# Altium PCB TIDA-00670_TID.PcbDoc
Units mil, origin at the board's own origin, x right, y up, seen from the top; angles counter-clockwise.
Board outline 1400 x 2800 mil, 2 copper layers (Top Layer, Bottom Layer), stack 62 mil thick; 53 components, 34 nets, 124 pads, 19 vias.
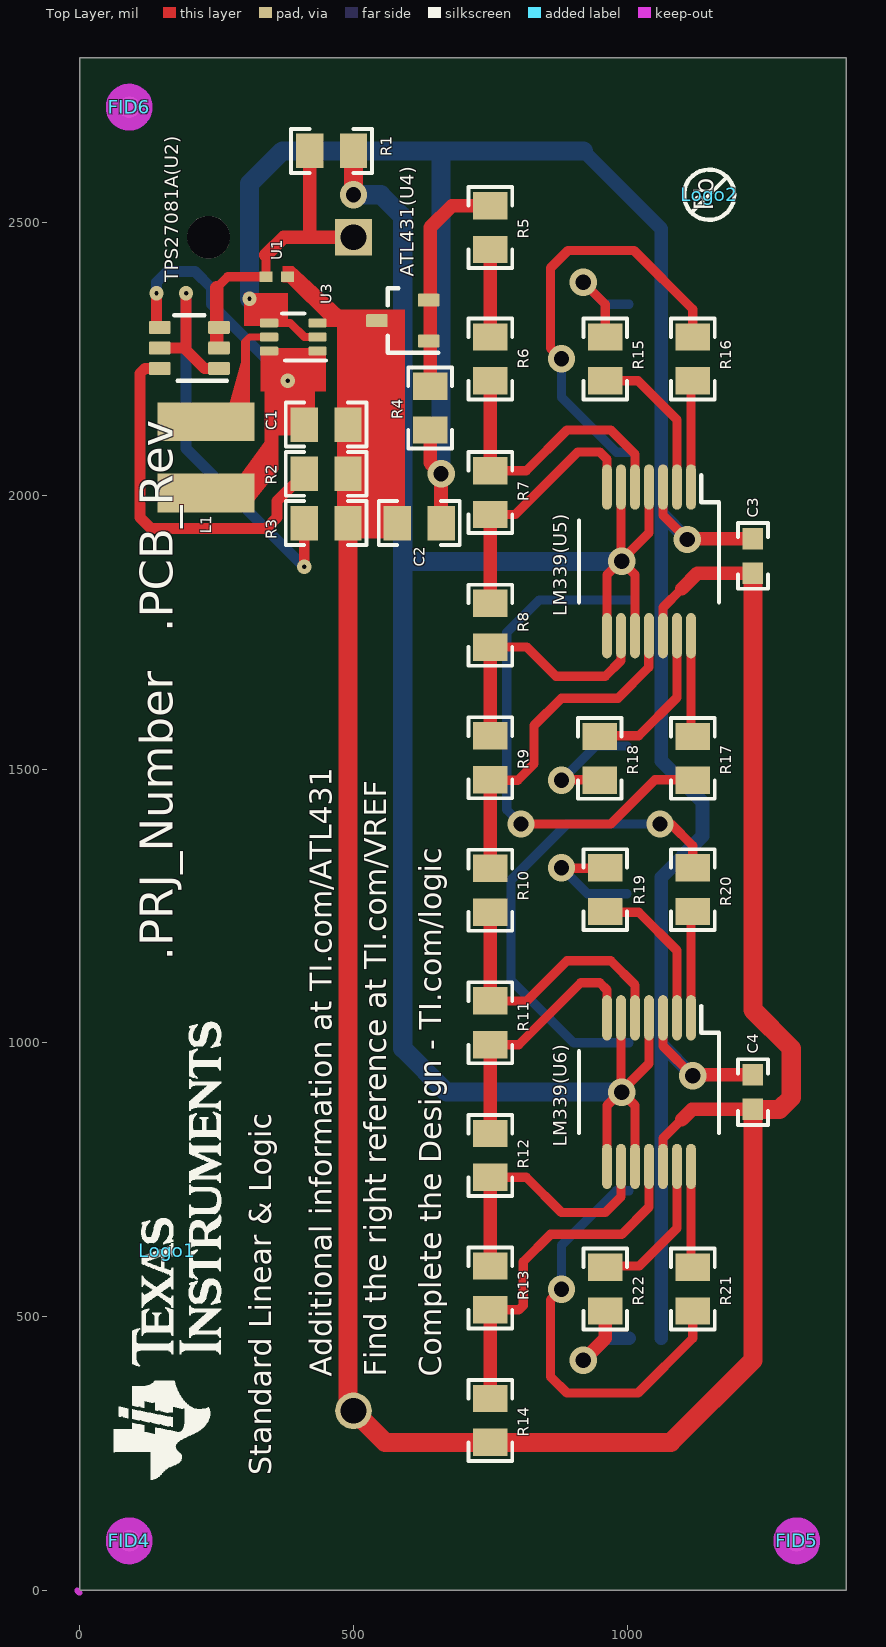
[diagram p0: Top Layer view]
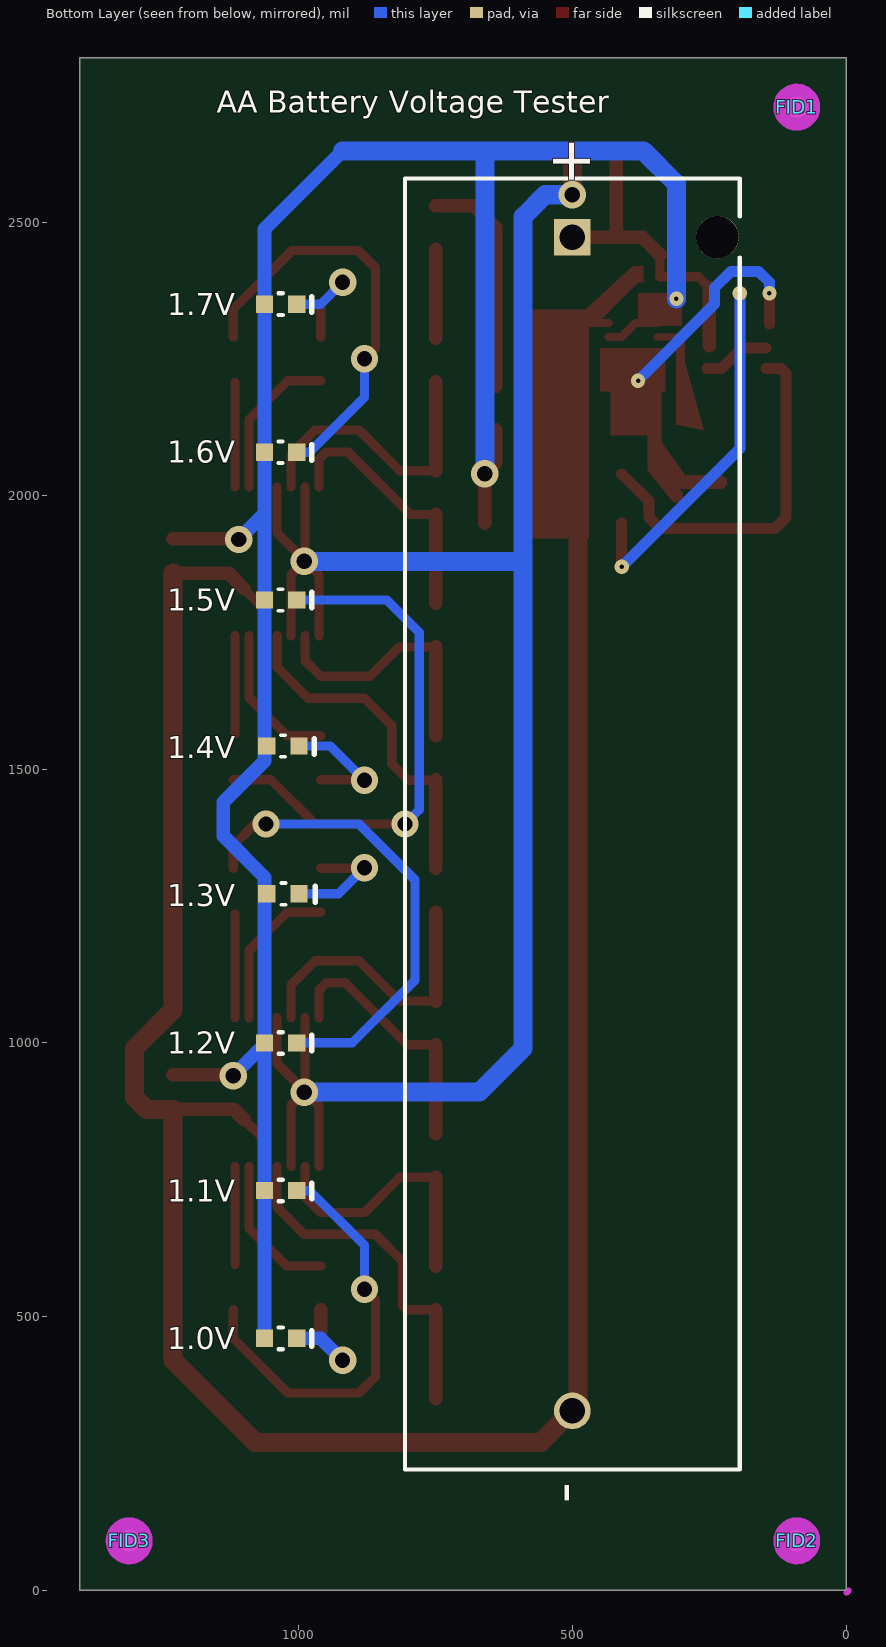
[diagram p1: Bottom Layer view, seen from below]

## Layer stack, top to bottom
Top Solder: solder mask 0.4, Solder Resist, Dk 3.5
Top Layer: signal copper 1.4
Dielectric1: core 59.2, FR-4, Dk 4.8
Bottom Layer: signal copper 1.4
Bottom Solder: solder mask 0.4, Solder Resist, Dk 3.5

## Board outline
0,0 0,2800 1400,2800 1400,0

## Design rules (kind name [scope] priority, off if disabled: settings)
AcuteAngle [All] p1: minimum=4.50000000000000E+0001 checktracksonly=FALSE
AssemblyTestPointUsage [All] p1: valid=2
Clearance Clearance_Keepouts [((IsTrack Or IsArc) And Not InPoly) And IsFree and IsKeepOut vs ((IsTrack Or IsArc) And Not InPoly) And IsFree and IsKeepOut] p1: gap=0
Clearance Clearance_BoardEdge_MountingHoles [OnCopper and InComponentClass('Mounting Holes') vs IsKeepOut] p2: gap=40
Clearance Clearance_BoardEdge_Poly [OnCopper and InPoly vs IsKeepOut] p3: gap=25
Clearance Clearance_BoardEdge [OnCopper and Not InComponentClass('Logo') and not InComponentClass('FiducialMark') and not InRegion(1000,500,4000,800) and Not IsKeepout vs IsKeepOut] p4: gap=75
Clearance Clearance_Poly [InPolygon] p5: gap=25
Clearance [All] p6: gap=7.87
ComponentClearance ComponentClearance_MountingHoles_FiducialMarks [InComponentClass('Mounting Holes') vs InComponentClass('FiducialMark')] p1: gap=50 collisioncheckmode=3 verticalgap=10 showdistances=FALSE
ComponentClearance ComponentClearance_Shunt [InComponentClass('Header') vs InComponentClass('Shunt')] p2: gap=0 collisioncheckmode=3 verticalgap=0 showdistances=FALSE
ComponentClearance ComponentClearance_Logo [InComponentClass('Logo')] p3: gap=50 collisioncheckmode=3 verticalgap=10 showdistances=FALSE
ComponentClearance ComponentClearance_ScrewToNut [(HasFootprint('NY PMS 440 0025 PH')) vs (HasFootprint('Keystone_1902C'))] p4: gap=5 collisioncheckmode=3 verticalgap=10 showdistances=FALSE
ComponentClearance ComponentClearance_MountingHoles [InComponentClass('Mounting Holes')] p5: gap=250 collisioncheckmode=3 verticalgap=100000 showdistances=FALSE
ComponentClearance ComponentClearance_SmallPassives [HasFootprint('0201*') or HasFootprint('0402*') or HasFootprint('0508') or HasFootprint('0603*') or HasFootprint('0612') or HasFootprint('0805*') or HasFootprint('0815*') or HasFootprint('0830*') or HasFootprint('1206*') or HasFootprint('1210*') or HasFootprint('1808*') or HasFootprint('1812*') or HasFootprint('1825*') or HasFootprint('2010*') or HasFootprint('2220*') or HasFootprint('2225*') or HasFootprint('2512*') or HasFootprint('2728*') or HasFootprint('3518*') vs HasFootprint('0201*') or HasFootprint('0402*') or HasFootprint('0508') or HasFootprint('0603*') or HasFootprint('0612') or HasFootprint('0805*') or HasFootprint('0815*') or HasFootprint('0830*') or HasFootprint('1206*') or HasFootprint('1210*') or HasFootprint('1808*') or HasFootprint('1812*') or HasFootprint('1825*') or HasFootprint('2010*') or HasFootprint('2220*') or HasFootprint('2225*') or HasFootprint('2512*') or HasFootprint('2728*') or HasFootprint('3518*')] p6: gap=20 collisioncheckmode=3 verticalgap=10 showdistances=FALSE
ComponentClearance ComponentClearance_THtoSMT [IsThruComponent vs IsSMTComponent] p7: gap=100 collisioncheckmode=3 verticalgap=30 showdistances=FALSE
ComponentClearance ComponentClearance_THtoTH [IsThruComponent vs IsThruComponent] p8: gap=118.11 collisioncheckmode=3 verticalgap=30 showdistances=FALSE
ComponentClearance [All] p9: gap=40 collisioncheckmode=3 verticalgap=10 showdistances=FALSE
DiffPairsRouting [All] p1: maxlimit=100 minlimit=10 mostfreqgap=10 toplayer_minwidth=15 toplayer_maxwidth=15 toplayer_prefwidth=15 bottomlayer_minwidth=15 bottomlayer_maxwidth=15 bottomlayer_prefwidth=15 maxuncoupledlength=1000
FabricationTestPointUsage TestPointUsage [All] p1: valid=2 allowmultiple=FALSE
FabricationTestpoint Testpoint [All] p1: side=3 testpointundercomponent=TRUE minsize=40 maxsize=100 preferedsize=60 minholesize=0 maxholesize=40 preferedholesize=32 testpointgrid=1 allowsidetop=TRUE allowsidebottom=TRUE usegrid=TRUE gridtolerance=0.01
FanoutControl Fanout_LCC [IsLCC] p1: bgadir=Out bgaviamode=Centered fanoutstyle=Auto fanoutdirection=Alternating viagrid=1 // Fanout_LCC (Default Rule)
FanoutControl Fanout_BGA [IsBGA] p2: bgadir=Out bgaviamode=Centered fanoutstyle=Auto fanoutdirection=Alternating viagrid=1 // Fanout_BGA (Default Rule)
FanoutControl Fanout_Default [All] p4: bgadir=Out bgaviamode=Centered fanoutstyle=Auto fanoutdirection=Alternating viagrid=1 // Fanout_Default (Default Rule)
FanoutControl Fanout_Small [(CompPinCount < 5)] p5: bgadir=Out bgaviamode=Centered fanoutstyle=Auto fanoutdirection=OutThenIn viagrid=1 // Fanout_Small (Default Rule)
HoleSize [All] p1: absolutevalues=TRUE maxlimit=251 minlimit=8 maxpercent=80.000 minpercent=20.000
MinimumAnnularRing MinimumAnnularRing_ThermalPadVias [IsVia and InAnyComponent] p1: minimumring=5.91
MinimumAnnularRing [All] p2: minimumring=9
MinimumSolderMaskSliver MinimumSolderMaskSliver_Logo [InComponentClass('Logo') vs InComponentClass('Logo')] p1: minsoldermaskwidth=0.7
MinimumSolderMaskSliver [All] p2: minsoldermaskwidth=3.94
PlaneConnect [All] p1: planeconnectstyle=Relief reliefexpansion=10 reliefentries=4 reliefconductorwidth=10 reliefairgap=10
PolygonConnect [All] p1: connectstyle=Relief reliefconductorwidth=10 reliefentries=4 polygonreliefangle="90 Angle" airgapwidth=10
RoutingVias ThermalPadVias [IsVia and InAnyComponent] p1: holewidth=7.87 width=19.68 viastyle="Through Hole" minholewidth=7.87 minwidth=19.68 maxholewidth=12.99 maxwidth=23.62
RoutingVias [All] p2: holewidth=16 width=34 viastyle="Through Hole" minholewidth=7.87 minwidth=26 maxholewidth=40 maxwidth=65
SilkToBoardRegionClearance [Not ((IsComment or IsDesignator) And (Hide <> 'False')) and not InRegion(1000,500,4000,800)] p1:
SilkToSilkClearance SilkToSilkClearance_Pb-FreeLogo [(HasFootprint('Pb-Free_Overlay_Medium') OR HasFootprint('Pb-Free_Overlay_Small')) vs (HasFootprint('Pb-Free_Overlay_Medium') OR HasFootprint('Pb-Free_Overlay_Small'))] p1: silktosilkclearance=0
SilkToSilkClearance [All] p2: silktosilkclearance=4
SilkToSolderMaskClearance "Silk to Solder Mask Opening" [All] p1: minsilkscreentomaskgap=4 clearancetoexposedcopper=FALSE
SolderMaskExpansion [All] p1: expansion=1.97
UnpouredPolygon [All] p1: allowunpoured=FALSE
Width [All] p1: maxlimit=100 minlimit=6 preferedwidth=10 checkconnectedcopper=TRUE
14 further rules are at their usual default settings.

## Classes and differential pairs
component class AssemblyNote: ZZ1 ZZ2 ZZ3
component class FiducialMark: FID1 FID2 FID3 FID4 FID5 FID6
component class TIDA-00670_TID_Hardware: FID1 FID2 FID3 FID4 FID5 FID6 Logo1 Logo2 ZZ1 ZZ2 ZZ3
component class Logo: Logo1
component class TIDA-00670_BlankSheet: 1.0V 1.1V 1.2V 1.3V 1.4V 1.5V 1.6V 1.7V "AA Battery Voltage Tester" ATL431(U4) C1 C2 C3 C4 L1 LM339(U5) LM339(U6) R1 R2 R3 R4 R5 R6 R7 R8 R9 R10 R11 R12 R13 R14 R15 R16 R17 R18 R19 R20 R21 R22 TPS27081A(U2) U1 U3

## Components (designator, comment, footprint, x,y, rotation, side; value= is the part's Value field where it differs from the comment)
1.0V "LS L29K-G1J2-1-Z" "LS L29K_Red" 1033.11,460 r180 bottom (schematic designator D8)
1.1V "LS L29K-G1J2-1-Z" "LS L29K_Red" 1033.11,730 r180 bottom (schematic designator D7)
1.2V "LS L29K-G1J2-1-Z" "LS L29K_Red" 1033.11,1000 r180 bottom (schematic designator D6)
1.3V "LO L29K-J2L1-24-Z" "LO L29K_Orange" 1029.17,1272.44 r180 bottom (schematic designator D5)
1.4V "LY L29K-H1K2-26-Z" "LY L29K_Yellow" 1029.17,1542.44 r180 bottom (schematic designator D4)
1.5V "LG L29K-G2J1-24-Z" "LG L29K_GREEN" 1033.11,1809.41 r180 bottom (schematic designator D3)
1.6V "LG L29K-G2J1-24-Z" "LG L29K_GREEN" 1033.11,2079.41 r180 bottom (schematic designator D2)
1.7V "LS L29K-G1J2-1-Z" "LS L29K_Red" 1033.11,2350 r180 bottom (schematic designator D1)
"AA Battery Voltage Tester" "1015" Keystone_1015 500,1400 r270 bottom locked (schematic designator BT1)
ATL431(U4) "ATL431AIDBZR" DBZ0003A_N 590,2320 r180 top (schematic designator U4)
C1 "C2012X5R0J106M" 0805_HV 450,2130 r0 top
C2 "C2012X5R0J106M" 0805_HV 620,1950 r180 top
C3 "GRM188R70J104KA01D" 0603 1230,1890 r270 top
C4 "GRM188R70J104KA01D" 0603 1230,910 r270 top
FID1 "Fiducial" Fiducial10-20 90,2710 r180 bottom
FID2 "Fiducial" Fiducial10-20 90,90 r180 bottom
FID3 "Fiducial" Fiducial10-20 1310,90 r180 bottom
FID4 "Fiducial" Fiducial10-20 90,90 r0 top
FID5 "Fiducial" Fiducial10-20 1310,90 r0 top
FID6 "Fiducial" Fiducial10-20 90,2710 r0 top
L1 "SDR0403-4R7ML" SDR0403 230,2070 r90 top
LM339(U5) "LM339DB" DB0014A_N 1040,1880 r270 top (schematic designator U5)
LM339(U6) "LM339DB" DB0014A_N 1040,910 r270 top (schematic designator U6)
Logo1 "Texas Instruments" TI_Stacked_Overlay_Small 160,620 r90 top
Logo2 "Pb-Free Symbol" Pb-Free_Overlay_Small 1150,2550 r90 top
R1 "ERJ-6GEYJ102V" 0805_HV 460,2630 r0 top
R2 "ERJ-6GEYJ102V" 0805_HV 450,2040 r180 top
R3 "ERJ-6GEYJ102V" 0805_HV 450,1950 r180 top
R4 "ERJ-6ENF2941V" 0805_HV 640,2160 r90 top
R5 "RR1220P-3651-D-M" 0805_HV 750,2490 r90 top
R6 "RR1220P-111-D" 0805_HV 750,2250 r90 top
R7 "RR1220P-471-D" 0805_HV 750,2005.55 r90 top
R8 "RR1220P-471-D" 0805_HV 750,1763.33 r90 top
R9 "RR1220P-471-D" 0805_HV 750,1521.11 r90 top
R10 "RR1220P-471-D" 0805_HV 750,1278.89 r90 top
R11 "RR1220P-471-D" 0805_HV 750,1036.67 r90 top
R12 "RR1220P-471-D" 0805_HV 750,794.44 r90 top
R13 "RR1220P-471-D" 0805_HV 750,552.22 r90 top
R14 "RR1220P-472-D" 0805_HV 750,310 r90 top
R15 "ERJ-6GEYJ751V" 0805_HV 960,2250 r90 top
R16 "ERJ-6GEYJ751V" 0805_HV 1120,2250 r90 top
R17 "ERJ-6GEYJ751V" 0805_HV 1120,1520 r270 top
R18 "ERJ-6GEYJ751V" 0805_HV 950,1520 r270 top
R19 "ERJ-6GEYJ751V" 0805_HV 960,1280 r90 top
R20 "ERJ-6GEYJ751V" 0805_HV 1120,1280 r90 top
R21 "ERJ-6GEYJ751V" 0805_HV 1120,550 r270 top
R22 "ERJ-6GEYJ751V" 0805_HV 960,550 r270 top
TPS27081A(U2) "TPS27081ADDCR" DDC0006A_N 200,2270 r180 top (schematic designator U2)
U1 "TPD1E10B06DPYR" DPY0002A 360,2400 r0 top
U3 "TLV61225DCKR" DCK0006A_N 390,2290 r180 top
ZZ1 "These assemblies are ESD sensitive, ESD precautions shall be observed." AssemblyNote 185,3829.11 r0 top
ZZ2 "These assemblies must be clean and free from flux and all contaminants. Use of no clean flux is not acceptable." AssemblyNote 185,3740.56 r0 top
ZZ3 "These assemblies must comply with workmanship standards IPC-A-610 Class 2, unless otherwise specified." AssemblyNote 185,3652 r0 top

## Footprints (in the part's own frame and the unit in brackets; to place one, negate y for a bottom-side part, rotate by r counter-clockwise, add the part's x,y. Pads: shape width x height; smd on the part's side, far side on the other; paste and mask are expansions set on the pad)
0603 [mm] "0603 from SM-752 data"
  rect 1x0.95 smd: 1(-0.8,0) 2(0.8,0)
  silkscreen extent -1.52,-0.69 1.52,0.69, body extent -0.87,-0.47 0.87,0.47, height 0.85
0805_HV [mil] "0805 with 30mil clearance between pads"
  rect 50x63 smd: 1(-40,0) 2(40,0)
  silkscreen extent -74,-40 74,40, body extent -43,-29 43,29, height 57
AssemblyNote [mil] "Assembly Note"
DB0014A_N [mm] "SOP, 14-Leads, Body 6.2x5.3mm, Pitch 0.65mm, IPC Medium Density"
  oval 2.1x0.45 smd: 1(-3.45,1.95) 2(-3.45,1.3) 3(-3.45,0.65) 4(-3.45,0) 5(-3.45,-0.65) 6(-3.45,-1.3) 7(-3.45,-1.95) 8(3.45,-1.95) 9(3.45,-1.3) 10(3.45,-0.65) 11(3.45,0) 12(3.45,0.65) 13(3.45,1.3) 14(3.45,1.95)
  silkscreen extent -4,-3.25 1.9,3.25, body extent -3.91,-3.1 3.91,3.1, height 2
DBZ0003A_N [mm] "SOT23, 3-Leads, Body 2.9x1.3mm, Pitch 0.95mm, Lead Span 2.4mm, IPC Medium Density"
  rrect17% 1x0.6 smd: 1(-1.2,0.95) 2(-1.2,-0.95) 3(1.2,0)
  silkscreen extent -1.65,-1.5 0.7,1.5, body extent -1.26,-1.46 1.26,1.46, height 0.98
DCK0006A_N [mm] "SOT23, 6-Leads, Body 2x1.3mm, Pitch 0.65mm, Lead Span 2.1mm, IPC Medium Density"
  rrect25% 0.85x0.4 smd: 1(-1.125,0.65) 2(-1.125,0) 3(-1.125,-0.65) 4(1.125,-0.65) 5(1.125,0) 6(1.125,0.65)
  silkscreen extent -1.5,-1.09 0.51,1.09, body extent -1.14,-1 1.14,1, height 0.95
DDC0006A_N [mm]
  rrect17% 1x0.6 smd: 1(-1.375,0.95) 2(-1.375,0) 3(-1.375,-0.95) 4(1.375,-0.95) 5(1.375,0) 6(1.375,0.95)
  silkscreen extent -1.75,-1.52 0.7,1.53, body extent -1.43,-1.48 1.43,1.49, height 0.92
DPY0002A [mm] "R-PX2SON-N2"
  rect 0.6x0.5 smd: 1(-0.5,0) 2(0.5,0)
  body extent -0.55,-0.35 0.55,0.35, height 0.4
Fiducial10-20 [mm]
  round 1 smd mask+0.5: 1(0,0)
  Top Layer keep-out circle w1.178: c0,0 r0.5
Keystone_1015 [mm] "AA Battery Holder, Through-hole mount"
  rect 1.7x1.7 hole 1.19: 1(-27.24,0)
  round 1.7 hole 1.19: 2(27.24,0)
  round 1.98 hole 1.98 unplated paste+0 mask+0: MH1(-27.24,6.73)
  silkscreen extent -29.97,-7.77 29.97,7.77, body extent -30,-7.74 29.93,7.8, height 14.86
"LG L29K_GREEN" [mm] "OSRAM"
  rect 0.8x0.8 smd paste-0.4: 1(-0.75,0) 2(0.75,0)
  silkscreen extent -0.1,-0.5 1.45,0.5, body extent -0.9,-0.45 0.9,0.45, height 0.67
"LO L29K_Orange" [mm] "SMD, 2-Leads, Body 1.3x0.8mm"
  rect 0.8x0.8 smd paste-0.4: 1(-0.75,0) 2(0.75,0)
  silkscreen extent -0.07,-0.5 1.5,0.5, body extent -0.9,-0.45 0.9,0.45, height 0.67
"LS L29K_Red" [mm] "SMD, 2-Leads, Body 1.3x0.8mm"
  rect 0.8x0.8 smd paste-0.4: 1(-0.75,0) 2(0.75,0)
  silkscreen extent -0.1,-0.5 1.45,0.5, body extent -0.9,-0.45 0.9,0.45, height 0.67
"LY L29K_Yellow" [mm] "OSRAM"
  rect 0.8x0.8 smd paste-0.4: 1(-0.75,0) 2(0.75,0)
  silkscreen extent -0.1,-0.5 1.45,0.5, body extent -0.9,-0.45 0.9,0.45, height 0.67
Pb-Free_Overlay_Small [mil]
  silkscreen extent -46,-46 46,46
SDR0403 [mm] "BOURNS"
  rect 1.8x4.5 smd: 1(-1.65,0) 2(1.65,0)
  body extent -2.41,-2.41 2.41,2.41, height 3.3
TI_Stacked_Overlay_Small [mil]
  silkscreen extent -418,-98 418,98

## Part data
1.0V 1.1V 1.2V 1.7V: "LED, Red, SMD"
1.3V: "LED, Orange, SMD"
1.4V: "LED, Yellow, SMD"
1.5V 1.6V: "LED, Green, SMD"
"AA Battery Voltage Tester": "AA Battery Holder, Through-hole mount"
ATL431(U4): "2.5V Low Iq Adjustable Precision Shunt Regulator, DBZ0003A"
C1 C2: "CAP, CERM, 10 µF, 6.3 V, +/- 20%, X5R, 0805"
C3 C4: "CAP, CERM, 0.1 µF, 6.3 V, +/- 10%, X7R, 0603"
FID1 FID2 FID3 FID4 FID5 FID6: "Fiducial mark.  There is nothing to buy or mount."
L1: "Inductor, Drum Core, Ferrite, 4.7 µH, 1.7 A, 0.094 ohm, SMD"
LM339(U5) LM339(U6): "Quad Comparator, DB0014A"
Logo1: library part TI_Logo, "Texas Instrument Corporate Signature"
Logo2: library part Pb-Free
R1 R2 R3: "RES, 1.0 k, 5%, 0.125 W, 0805"
R4: "RES, 2.94 k, 1%, 0.125 W, 0805"
R5: "RES, 3.65 k, 0.5%, 0.1 W, 0805"
R6: "RES, 110, 0.5%, 0.1 W, 0805"
R7 R8 R9 R10 R11 R12 R13: "RES, 470, 0.5%, 0.1 W, 0805"
R14: "RES, 4.70 k, 0.5%, 0.1 W, 0805"
R15 R16 R17 R18 R19 R20 R21 R22: "RES, 750, 5%, 0.125 W, 0805"
TPS27081A(U2): "1.2V - 8V, 3A PFET High Side Load Switch with Level Shift & Adjustable Slew Rate Control, DDC0006A"
U1: "ESD in 0402 Package with 10 pF Capacitance and 6 V Breakdown, 1 Channel, -40 to +125 degC, 2-pin X2SON (DPY), Green (RoHS & no Sb/Br)"
U3: "SINGLE CELL HIGH EFFICIENT STEP-UP CONVERTER, DCK0006A"
ZZ1 ZZ2 ZZ3: library part AssemblyNote

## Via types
v1: diameter 50, hole 28, Top Layer to Bottom Layer, 14 vias
v2: diameter 26, hole 8, Top Layer to Bottom Layer, 5 vias

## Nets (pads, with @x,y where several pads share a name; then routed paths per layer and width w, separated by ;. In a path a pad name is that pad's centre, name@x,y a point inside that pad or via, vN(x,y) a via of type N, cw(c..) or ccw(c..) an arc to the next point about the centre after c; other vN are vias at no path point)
+2V5: ATL431(U4).1 ATL431(U4).2 R4.2 R5.2 | length 416.6
  Top Layer w25: R4.2 640,2490 680,2530 R5.2
+3V3: 1.0V.1 1.1V.1 1.2V.1 1.3V.1 1.4V.1 1.5V.1 1.6V.1 1.7V.1 C2.1 C3.1 C4.1 LM339(U5).3 LM339(U6).3 R4.1 U3.2 U3.4 | length 4601.4
  Top Layer w15: U3.4 384.41,2315.59 410,2290 U3.2
  Top Layer w17: 1065.59,1045.83 1065.59,994.41 v1(1120,940) ; 1065.59,2015.83 1065.59,1964.41 v1(1110,1920)
  Top Layer w25: R4.1 640,2060 v1(660,2040) ; C2.1 v1@660,2020 ; v1@1111.5,1921.5 C3.1 ; v1@1121.5,941.5 C4.1
  Bottom Layer w25: 920,2630 1062.64,2487.36 1.7V.1 1.6V.1 1062.64,1967.36 ; 1.0V.1 1.1V.1 1.2V.1@1062.64,997.36 ; v1(1110,1920) 1062.64,1967.36 ; v1(1120,940) 1.2V.1@1062.64,997.36 ; 1.2V.1@1062.64,997.36 1.2V.1 1062.64,1302.64 1137.8,1377.8 1137.8,1440 1062.64,1515.17 1.5V.1 1062.64,1967.36
  Bottom Layer w35: v2(310,2360) 310,2570 370,2630 660,2630 ; v1(660,2040) 660,2630 ; 920,2630 660,2630
BATT: LM339(U5).4 LM339(U5).6 LM339(U5).8 LM339(U5).10 LM339(U6).4 LM339(U6).6 LM339(U6).8 LM339(U6).10 R1.2 | length 3711.1
  Top Layer w17: 963.23,774.17 963.23,885.59 v1@988.82,911.18 ; 963.23,1744.17 963.23,1855.59 v1@988.82,1881.18 ; 988.82,1045.83 v1@988.82,911.18 ; 988.82,2015.83 v1@988.82,1881.18 ; 1014.41,774.17 1014.41,885.59 v1(990,910) v1@988.82,911.18 ; 1014.41,1744.17 1014.41,1855.59 v1(990,1880) v1@988.82,1881.18 ; 1040,1045.83 1040,962.36 v1@988.82,911.18 ; 1040,2015.83 1040,1932.36 v1@988.82,1881.18
  Top Layer w35: v1(500,2550) R1.2
  Bottom Layer w35: v1(500,2550) 550,2550 590,2510 590,1950 590,990 670,910 v1(990,910) ; 590,1880 v1(990,1880)
GND: "AA Battery Voltage Tester.2" ATL431(U4).3 C1.2 C2.2 C3.2 C4.2 LM339(U5).12 LM339(U6).12 R2.1 R3.1 R14.1 U1.2 U3.3 | length 4632.4
  Top Layer w15: U1.2 464.09,2315.59 ; U3.3 464.09,2315.59 ; 500.27,2315.59 464.09,2315.59
  Top Layer w17: 1065.59,774.17 1065.59,825.59 1100,860 ; 1065.59,1744.17 1065.59,1795.59 1100,1830
  Top Layer w25: 490,337.56 500,327.56 ; 1100,860 1118.5,878.5 C4.2 ; 1100,1830 1128.5,1858.5 C3.2
  Top Layer w35: 490,337.56 R3.1 ; 500,327.56 557.56,270 R14.1 1080,270 1230,420 C4.2 1278.5,878.5 1300,900 1300,990 1230,1060 C3.2
Net1.0V(D8)_2: 1.0V.2 R22.2 | length 208.9
  Top Layer w25: v1(920,420) 960,460 R22.2@960,512.22
  Bottom Layer w25: v1(920,420) 960,460 1.0V.2
Net1.1V(D7)_2: 1.1V.2 R21.2 | length 779.4
  Top Layer w17: v1(880,550) 860,530 860,390 890,360 1020,360 1120,460 R21.2@1120,512.22
  Bottom Layer w17: v1(880,550) 880,630 980,730 1.1V.2
Net1.2V(D6)_2: 1.2V.2 R20.2 | length 878.9
  Top Layer w17: v1(1060,1400) 1080,1400 1120,1360 R20.2@1120,1318.89
  Bottom Layer w17: 1.2V.2 902.2,1000 787.65,1114.56 787.65,1297.65 890,1400 v1(1060,1400)
Net1.3V(D5)_2: 1.3V.2 R19.2 | length 218.2
  Top Layer w17: v1@881.11,1318.89 R19.2@960,1318.89
  Bottom Layer w17: v1(880,1320) 927.56,1272.44 1.3V.2
Net1.4V(D4)_2: 1.4V.2 R18.2 | length 224.4
  Top Layer w17: v1@881.11,1481.11 R18.2@960,1481.11
  Bottom Layer w17: v1(880,1480) 942.44,1542.44 1.4V.2
Net1.5V(D3)_2: 1.5V.2 R17.2 | length 956.6
  Top Layer w17: v1(805.99,1399.99) 969.99,1399.99 1051.11,1481.11 R17.2@1120,1481.11
  Bottom Layer w17: v1(805.99,1399.99) 780,1425.97 780,1750 839.41,1809.41 1.5V.2
Net1.6V(D2)_2: 1.6V.2 R16.2 | length 777.9
  Top Layer w17: v1(880,2250) 860,2270 860,2415.97 892.01,2447.99 1012.62,2447.99 1120,2340.61 R16.2
  Bottom Layer w17: v1(880,2250) 880,2180 980.59,2079.41 1.6V.2
Net1.7V(D1)_2: 1.7V.2 R15.2 | length 216.7
  Top Layer w17: v1(920,2390) 960,2350 R15.2
  Bottom Layer w17: v1(920,2390) 960,2350 1.7V.2
NetBT1_1: "AA Battery Voltage Tester.1" R1.1 TPS27081A(U2).2 TPS27081A(U2).3 U1.1 | length 575.1
  Top Layer w17: 250,2380 270,2400 U1.1 ; U1.1@340,2400.32 340,2440
  Top Layer w25: 250,2274.13 250,2380 ; 340,2440 372.44,2472.44 420,2472.44 ; R1.1 420,2472.44 ; 500,2472.44 420,2472.44
NetC1_1: C1.1 L1.1 TPS27081A(U2).4 U3.1 U3.6 | length 754.5
  Top Layer w20: 140,2313.27 v2(140,2370)
  Top Layer w25: L1.1@230,2025.04 325.04,2025.04 ; L1.1@310,2000 350,2050 350,2220
  Bottom Layer w20: v2(140,2370) 140,2390 160,2410 210,2410 240,2380 240,2350 v2(380,2210)
NetL1_2: L1.2 U3.5 | length 179.9
  Top Layer w12: L1.2@300,2150 300,2280 310,2290 U3.5
NetR2_2: R2.2 TPS27081A(U2).6 | length 670.5
  Top Layer w20: 145.87,2232.6 118.94,2232.6 110,2223.66 110,1960 130,1940 340,1940 360,1960 360,1990 R2.2
NetR3_2: R3.2 TPS27081A(U2).1 TPS27081A(U2).5 | length 894.9
  Top Layer w20: 145.87,2270 190,2270 ; v2(194.01,2370) 194.01,2274.01 190,2270 ; 254.13,2232.6 227.4,2232.6 190,2270 ; v2(410,1870) R3.2
  Bottom Layer w20: v2(194.01,2370) 194.01,2085.99 v2(410,1870)
NetR5_1: R5.1 R6.2 | length 162.2
  Top Layer w25: R6.2@750,2287.78 R5.1
NetR6_1: LM339(U5).5 R6.1 R7.2 | length 535.6
  Top Layer w17: R7.2 815.55,2045.55 890,2120 970,2120 1014.41,2075.59 1014.41,2015.83
  Top Layer w25: R7.2 R6.1@750,2207.78
NetR7_1: LM339(U5).7 R7.1 R8.2 | length 479.3
  Top Layer w17: R7.1 795.55,1965.55 910,2080 950,2080 963.23,2066.77 963.23,2015.83
  Top Layer w25: R8.2 R7.1
NetR8_1: LM339(U5).9 R8.1 R9.2 | length 480.4
  Top Layer w17: R8.1 816.67,1723.33 870,1670 960,1670 988.82,1698.82 988.82,1744.17
  Top Layer w25: R9.2 R8.1
NetR9_1: LM339(U5).11 R9.1 R10.2 | length 635.1
  Top Layer w17: R9.1@751.11,1480 800,1480 830,1510 830,1580 880,1630 983.18,1630 1039.64,1686.46 1039.64,1743.81 1040,1744.17
  Top Layer w25: R10.2 R9.1
NetR10_1: LM339(U6).5 R10.1 R11.2 | length 535.2
  Top Layer w17: R11.2 816.67,1076.67 890,1150 970,1150 1014.41,1105.59 1014.41,1045.83
  Top Layer w25: R11.2 R10.1
NetR11_1: LM339(U6).7 R11.1 R12.2 | length 478.8
  Top Layer w17: R11.1 801.86,996.67 915.2,1110 950,1110 963.23,1096.77 963.23,1045.83
  Top Layer w25: R12.2 R11.1
NetR12_1: LM339(U6).9 R12.1 R13.2 | length 495
  Top Layer w17: R12.1 815.56,754.44 880,690 960,690 988.82,718.82 988.82,774.17
  Top Layer w25: R13.2 R12.1
NetR13_1: LM339(U6).11 R13.1 R14.2 | length 651
  Top Layer w17: R13.1 802.22,512.22 810,520 810,600 860,650 990,650 1040,700 1040,774.17
  Top Layer w25: R14.2 R13.1
NetR15_1: LM339(U5).2 R15.1 | length 283.7
  Top Layer w17: R15.1 1020,2210 1091.18,2138.82 1091.18,2015.83
NetR16_1: LM339(U5).1 R16.1 | length 190.9
  Top Layer w17: 1116.77,2015.83 R16.1@1116.77,2206.77
NetR17_1: LM339(U5).14 R17.1 | length 179.8
  Top Layer w17: R17.1@1116.77,1564.34 1116.77,1744.17
NetR18_1: LM339(U5).13 R18.1 | length 273.2
  Top Layer w17: R18.1@960,1561.11 1021.11,1561.11 1091.18,1631.18 1091.18,1744.17
NetR19_1: LM339(U6).2 R19.1 | length 283.2
  Top Layer w17: R19.1@960,1238.89 1021.11,1238.89 1091.18,1168.82 1091.18,1045.83
NetR20_1: LM339(U6).1 R20.1 | length 189.8
  Top Layer w17: 1116.77,1045.83 R20.1@1116.77,1235.66
NetR21_1: LM339(U6).14 R21.1 | length 178.7
  Top Layer w17: R21.1@1116.77,595.45 1116.77,774.17
NetR22_1: LM339(U6).13 R22.1 | length 272.7
  Top Layer w17: R22.1@960,592.22 1022.22,592.22 1091.18,661.18 1091.18,774.17
pads on no net: "AA Battery Voltage Tester.MH1" FID1.1 FID2.1 FID3.1 FID4.1 FID5.1 FID6.1

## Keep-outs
Keep-Out Layer:
  lines w10: -5,0 ccw(c0,0) 0,-5 cw(c0,0) -5,0 ; 4950,3455 cw(c4950,3450) 4955,3450 ccw(c4950,3450) 4950,3455
  text ".Layer_Name" at 577,-858.49 h60

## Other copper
Top Layer:
  rectangle net +3V3: 300,2310 380,2370
  rectangle net NetC1_1: 330,2190 450,2270
  rectangle net NetC1_1: 340,2110 430,2190
  rectangle net GND: 470,1921.48 594.39,2340
  region net GND: 486.25,2300.29 501.95,2317.42 390,2420 374.3,2402.86
  rectangle net GND: 370,2389.68 390,2420
  region net NetL1_2: 310,2290 310,2170 310,2130 260,2120 307.32,2290.36
  region net NetC1_1: 340.31,2101.95 340.31,2031.95 293.59,2031.95 279.69,2018.05
  text ".Layer_Name" at 577,-858.49 h60
Bottom Layer:
  text ".Layer_Name" at 577,-858.49 h60

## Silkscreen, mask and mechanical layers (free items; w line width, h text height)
Top Overlay:
  text "This document can handle board shapes up to 7.9in x 10in, although" at 120,6875 h60
  text "our panel vendors top out at 7in x 10in." at 120,6750.94 h60
  text "To re-size the board shape, do the following:" at 175,6626.88 h60
  text "Select lines on M1 Board Outline and delete (easy in single layer mode...shift+s)" at 235,6502.82 h60
  text "Draw a rectangle using lines (example will be for a 4\" x 6\" board" at 235,6378.76 h60
  text "Enter Place Line mode (keyboard pl)" at 445,6254.71 h60
  text "keyboard jo to jump to origin, hit enter" at 445,6130.65 h60
  text "keyboard jl to jump to location, set x to 6000, hit enter twice" at 445,6006.59 h60
  text "keyboard jl to jump to location, set x to 6000 and y to 4000, hit enter twice" at 445,5882.53 h60
  text "keyboard jl to jump to location, set x to 0 and y to 4000, hit enter twice" at 445,5758.47 h60
  text "keyboard jo to jump to origin, hit enter" at 445,5634.41 h60
  text "Hit ESC twice to exit place line mode" at 445,5510.35 h60
  text "Select lines on M1 Board Outline" at 235,5366.3 h60
  text "Menu Design|Board Shape|Define from Selected Objects (keyboard dsd)" at 235,5262.24 h60
  text "To define a Keep-Out that mirrors the board outline:" at 120,5138.18 h60
  text "Menu Design|Board Shape|Create Primitives From Board Shape (keyboard dsp)" at 235,5014.12 h60
  text "Set the Keep-Out Layer as the layer, set width as preferred" at 445,4890.06 h60
  text "Ensure Route Tool Outline is selected, hit enter" at 445,4766 h60
  text "If you re-size the board, don't forget to move the drill table strings on the" at 120,4443 h60
  text "Drill Drawing Layer...they should be just to the right of your board shape" at 313,4337 h60
  text ".PCB_Rev" at 170,1750 h60 r90
  text ".PRJ_Number" at 170,1150 h60 r90
  text "Additional information at TI.com/ATL431" at 460,390 h40 r90
  text "Find the right reference at TI.com/VREF" at 560,390 h40 r90
  text "Complete the Design - TI.com/logic" at 660,390 h40 r90
  text "Standard Linear & Logic" at 350,210 h40 r90
  text ".Layer_Name" at 577,-858.49 h60
Bottom Overlay:
  text ".Layer_Name" at 577,-858.49 h60
Top Paste:
  text ".Layer_Name" at 577,-858.49 h60
Bottom Paste:
  text ".Layer_Name" at 577,-858.49 h60
Top Solder:
  text ".Layer_Name" at 577,-858.49 h60
  text ".Layer_Name" at 577,-858.49 h60
Bottom Solder:
  text ".Layer_Name" at 577,-858.49 h60
Drill Guide:
  text ".Layer_Name" at 577,-858.49 h60
M1 Board Outline:
  lines w10: 0,0 0,2800 1400,2800 1400,0 0,0
  lines w47.24: -23.62,0 ccw(c0,0) 0,-23.62 ; -23.62,0 ccw(c0,0) 0,-23.62 ; -23.62,0 -23.62,2800 ; -23.62,2800 cw(c0,2800) 0,2823.62 ; -23.62,2800 cw(c0,2800) 0,2823.62 ; 0,-23.62 1400,-23.62 ; 0,2823.62 1400,2823.62 ; 1400,-23.62 ccw(c1400,0) 1423.62,0 ; 1400,-23.62 ccw(c1400,0) 1423.62,0 ; 1400,2823.62 cw(c1400,2800) 1423.62,2800 ; 1400,2823.62 cw(c1400,2800) 1423.62,2800 ; 1423.62,0 1423.62,2800
  text ".Layer_Name" at 577,-858.49 h60
M2 Board Dimensions:
  rectangle: 125,-400 500,-275
  rectangle: 0,-275 125,-150
  lines w7: 0,-275 1000,-275 ; 125,-400 125,-150 ; 250,-400 250,-150 ; 500,-400 500,-150 ; 750,-400 750,-150 ; 0,-400 0,-150 1000,-150 1000,-400 0,-400
  text ".Layer_Name" at 577,-858.49 h60
M3 3D STEP Top:
  text ".Layer_Name" at 577,-858.49 h60
M4 3D STEP Bottom:
  text ".Layer_Name" at 577,-858.49 h60
M5 Assembly Top:
  lines w10: -292,-930.17 6308,-930.17 ; -292,-726.83 6310,-726.83 ; -292,-523.5 -292,-1133.5 3713,-1133.5 6310,-1133.5 6310,-523.5 -291.5,-523.5 -291.5,-1133.5 1284,-1133.5 ; 2173,-1133.5 2173,-523.5 ; 3440,-726.83 3440,-523.5 ; 4280,-726.83 4280,-523.5 ; 4902,-1140 4902,-937.17
  text "COMPONENTS MARKED 'DNP' SHOULD NOT BE POPULATED." at 1153.5,-318.5 h60
  text "ASSEMBLY VARIANT:" at 1153,-434 h60
  text ".VariantName" at 2189,-434 h60
  text "PCB VIEWED FROM TOP SIDE" at -228.5,-655.67 h60
  text "BOARD #:" at 2248,-655.67 h60
  text ".PRJ_Number" at 2793.5,-655.67 h60
  text "REV:" at 3638,-655.67 h60
  text ".PCB_Rev" at 3929.5,-655.67 h60
  text "SVN REV:" at 4476,-655.67 h60
  text ".VersionControl_RevNumber" at 4982,-655.67 h60
  text "TID #:" at 2248,-859 h60
  text ".TID" at 2793.5,-859 h60
  text "PLOT NAME =" at -228.5,-1064.34 h60
  text ".plot_File_Name" at 577,-1064.34 h60
  text "GENERATED    :" at 2250,-1064.34 h60
  text ".Print_Date" at 3119.5,-1064.34 h60
  text ".Print_Time" at 3848.5,-1064.34 h60
  text "TEXAS INSTRUMENTS" at 5113,-1064.34 h60
M6 Assembly Bottom:
  lines w10: -292.5,-727.33 6309.5,-727.33 ; -290.5,-930.67 6309.5,-930.67 ; 1115.5,-1140.5 1115.5,-937.67 ; 1737.5,-727.33 1737.5,-524 ; 2577.5,-727.33 2577.5,-524 ; 3844.5,-1134 3844.5,-524 ; 4733.5,-1134 6309,-1134 6309,-524 -292.5,-524 -292.5,-1134 2304.5,-1134 6309.5,-1134 6309.5,-524
  text "COMPONENTS MARKED 'DNP' SHOULD NOT BE POPULATED." at 6102,-318 h60
  text ".VariantName" at 5058,-434 h60
  text "ASSEMBLY VARIANT:" at 6097,-434 h60
  text ".VersionControl_RevNumber" at 1035.5,-656.17 h60
  text "SVN REV:" at 1541.5,-656.17 h60
  text ".PCB_Rev" at 2088,-656.17 h60
  text "REV:" at 2379.5,-656.17 h60
  text ".PRJ_Number" at 3224,-656.17 h60
  text "BOARD #:" at 3769.5,-656.17 h60
  text "PCB VIEWED FROM BOTTOM SIDE" at 6246,-656.17 h60
  text ".TID" at 3224,-859.5 h60
  text "TID #:" at 3769.5,-859.5 h60
  text "TEXAS INSTRUMENTS" at 904.5,-1064.84 h60
  text ".Print_Time" at 2169,-1064.84 h60
  text ".Print_Date" at 2898,-1064.84 h60
  text "GENERATED    :" at 3767.5,-1064.84 h60
  text ".plot_File_Name" at 5440.5,-1064.84 h60
  text "PLOT NAME =" at 6246,-1064.84 h60
M9 Title Sheet:
  drawing of 57 lines, arcs and shapes, not listed
  text "1" at 739.84,8036.5 h70
  text "2" at 3235.5,8036.5 h70
  text "3" at 5724.84,8036.5 h70
  text "4" at 8231.51,8036.5 h70
  text "5" at 10730.5,8036.5 h70
  text "6" at 13235.5,8036.5 h70
  text "A" at -416.5,6893.5 h70
  text "A" at 14383.5,6893.5 h70
  text "B" at -416.5,4513.5 h70
  text "B" at 14383.5,4513.5 h70
  text "C" at -416.5,2138.5 h70
  text "C" at 14383.5,2138.5 h70
  text "PROJECT TITLE:" at 11343.5,277.5 h45
  text ".PRJ_Title" at 11393.5,144.17 h70
  text "DESIGNED FOR:" at 11343.5,-23.5 h45
  text ".PRJ_Customer" at 11393.5,-163.5 h70
  text "D" at -416.5,-231.5 h70
  text "D" at 14383.5,-231.5 h70
  text "FILE NAME:" at 11343.5,-323.5 h45
  text ".PCB_File_Name_No_Path" at 11393.5,-443.5 h70
  text "Texas Instruments (TI) and/or its licensors do not warrant the accuracy or completeness of this specification" at 6374,-605.34 h45
  text "ENGINEER:" at 11343.5,-613.5 h45
  text "LAYOUT BY:" at 12848.5,-613.5 h45
  text "or any information contained therein. TI and/or its licensors do not warrant that this design will meet" at 6329.01,-718 h45
  text ".PRJ_Engineer" at 11393.5,-768.49 h70
  text ".PCB_Layout" at 12899,-768.49 h70
  text "the specifications, will be suitable for your application or fit for any particular purpose, or will operate in" at 6329.01,-830.67 h45
  text ".Layer_Name" at 577,-858.49 h60
  text "ALTIUM DESIGNER VERSION:" at 12848.5,-923.5 h45
  text "an implementation. TI and/or its licensors do not warrant that the design is production worthy. You should" at 6329.01,-943.33 h45
  text "completely validate and test your design implementation to confirm the system functionality for your application." at 6374,-1056 h45
  text ".print_Scale" at 11393.5,-1056.83 h70
  text ".Application_BuildNumber" at 12899,-1056.83 h70
  text "1" at 739.84,-1263.5 h70
  text "2" at 3235.5,-1263.5 h70
  text "3" at 5724.84,-1263.5 h70
  text "4" at 8231.51,-1263.5 h70
  text "5" at 10730.5,-1263.5 h70
  text "6" at 13235.5,-1263.5 h70
M10 Fab Notes:
  drawing of 185 lines, arcs and shapes, not listed
  text "DESIGN INFORMATION" at 12381.02,5910 h60
  text "MIN. TRACK WIDTH:" at 11736.46,5730 h60
  text "8" at 12832.7,5730 h60
  text "MIL" at 12987.46,5730 h60
  text "MIN. CLEARANCE:" at 11736.46,5598 h60
  text "0.2" at 12772.7,5598 h60
  text "mm" at 12987.46,5598 h60
  text "MIN. VIA PAD SIZE:" at 11736.46,5466 h60
  text "24" at 12802.71,5466 h60
  text "MIL" at 12987.46,5466 h60
  text "0.05mm (2MIL)" at 12431.46,5324.29 h60
  text "MINIMUM ANNULAR RING" at 11407.23,5320 h60
  text "EXTERNAL" at 13139.46,5320 h60
  text "PER" at 11607.23,5202 h60
  text "IPC-D-275 CLASS 2 LEVEL C" at 11827.23,5202 h60
  text "MIL, HOLES" at 13315.46,5089.71 h60
  text "+/-" at 12923,5089 h60
  text "+/-" at 13777,5089 h60
  text "REGISTRATION TOLERANCES:" at 11407.23,5084 h60
  text "METAL" at 12607,5084 h60
  text "5" at 13183.2,5084 h60
  text "3" at 14016.2,5084 h60
  text "MIL" at 14132.46,5084 h60
  text "MATERIAL:" at 11332.46,4874.54 h60
  text "FR-4 High Tg" at 12318.9,4734.21 h60
  text "FR-408" at 11753.46,4725.64 h60
  text "X" at 12165.46,4725.64 h60
  text "OTHER" at 13241.46,4725.64 h60
  text "62 MIL (1.6mm) +/-10%" at 12073.56,4562.92 h60
  text "THICKNESS:" at 11407.23,4558.64 h60
  text "X" at 11945.4,4558.64 h60
  text "OTHER" at 13358.46,4558.64 h60
  text "TOLERANCE:" at 11407.23,4400.64 h60
  text "X" at 12246.53,4400.64 h60
  text "ANSI IPC-6012 TYPE 3 CLASS 2" at 12433.48,4400.64 h60
  text "OTHER +/-" at 12433.46,4244.64 h60
  text "BOW & TWIST:" at 11407.23,4087.64 h60
  text "X" at 12246.53,4087.64 h60
  text "ANSI IPC-6012 TYPE 3 CLASS 2" at 12433.48,4087.64 h60
  text "OTHER +/-" at 12433.46,3929.13 h60
  text "DRILLING:" at 11332.46,3790.64 h60
  text "REFERENCE:" at 11407.23,3673.64 h60
  text "X" at 12055.46,3673.64 h60
  text "AS SHOWN" at 12242.46,3673.64 h60
  text "X" at 12956.46,3673.64 h60
  text "NC_DRILL FILES" at 13093.46,3673.64 h60
  text "PTH MIN COPPER THICKNESS:" at 11407.23,3515.64 h60
  text "X" at 12757.46,3515.64 h60
  text "1MIL" at 12894.46,3515.64 h60
  text "OTHER" at 13391.46,3515.64 h60
  text "BOARD FINISH:" at 11332.46,3356.64 h60
  text "SILKSCREEN:" at 11487.68,3238.64 h60
  text "X" at 12436.46,3238.64 h60
  text "TOP" at 12562.46,3238.64 h60
  text "X" at 12946.46,3238.64 h60
  text "BOTTOM" at 13073.46,3238.64 h60
  text "SILKSCREEN COLOR:" at 11487.68,3071.64 h60
  text "X" at 12435.42,3071.64 h60
  text "WHITE" at 12562.46,3071.64 h60
  text "OTHER" at 13073.46,3071.64 h60
  text "SOLDER RESIST COLOR:" at 11487.68,2901.64 h60
  text "X" at 12055.42,2742.44 h60
  text "GREEN" at 12182.46,2742.44 h60
  text "BLUE" at 12773.46,2742.44 h60
  text "OTHER" at 13311.46,2742.44 h60
  text "IMMERSION GOLD (ENIG)" at 12393.46,2553.92 h60
  text "ENEPIG" at 13731,2550.64 h60
  text "SURFACE FINISH:" at 11332.46,2549.64 h60
  text "X" at 12206.51,2549.64 h60
  text "IMM. TIN/SILVER OR EQUIV" at 11662,2392.64 h60
  text "OTHER" at 13093.46,2392.64 h60
  text "ARRAY/PANEL:" at 11332.46,2213.64 h60
  text "CUT AND TRIM PER MECH LAYER 1" at 12393.46,2209.35 h60
  text "N.C. ROUTE" at 12393.46,2057.64 h60
  text "X" at 13072.46,2057.64 h60
  text "V. SCORE" at 13259.46,2057.64 h60
  text "CERTIFICATION:" at 11332.46,1920.64 h60
  text "MATERIALS AND WORKMANSHIP FOR ALL PCBS" at 12057.46,1920.64 h60
  text "TO MEET OR EXCEED THE REQUIREMENTS OF:" at 12057.46,1822.64 h60
  text "X" at 11683.96,1686.13 h60
  text "ANSI IPC-A-600F CLASS ->" at 11822.96,1686.13 h60
  text "X" at 13462.02,1686.13 h60
  text "2" at 13580.96,1686.14 h60
  text "1" at 13265.96,1684.64 h60
  text "3" at 13934.96,1684.64 h60
  text "X" at 11686.02,1526.64 h60
  text "UL 94V-0" at 11822.96,1526.64 h60
  text "X" at 12498.02,1526.64 h60
  text "RoHS" at 12634.96,1526.64 h60
  text "OTHER" at 13279.36,1526.64 h60
  text "PER ORDER" at 13676.42,1526.64 h60
  text "ADDITIONAL REQUIREMENTS:" at 11332.46,1385.64 h60
  text "MICROSECTION:" at 11407.23,1270.64 h60
  text "YES" at 12312.96,1270.64 h60
  text "REQUIRED" at 13174.46,1114.49 h60
  text "BARE BOARD ELEC. TEST:" at 11407.23,1111.64 h60
  text "NONE" at 12712.96,1111.64 h60
  text "X" at 13047.46,1111.64 h60
  text "PER ORDER" at 13766.46,1111.64 h60
  text "MANUFACTURER'S UL:" at 11407.23,954.64 h60
  text "RAIL" at 12572.96,950.35 h60
  text "METAL" at 13064.77,950.35 h60
  text "X" at 13440,950 h60
  text "SILK" at 13576.46,950.35 h60
  text ".Layer_Name" at 577,-858.49 h60
M11 Gerber Information:
  lines w10: -292,-930.17 6308,-930.17 ; -292,-726.83 6310,-726.83 ; -292,-523.5 -292,-1133.5 3713,-1133.5 6310,-1133.5 6310,-523.5 -291.5,-523.5 -291.5,-1133.5 1284,-1133.5 ; 2173,-1133.5 2173,-523.5 ; 3440,-726.83 3440,-523.5 ; 4280,-726.83 4280,-523.5 ; 4902,-1140 4902,-937.17
  text "ALL ARTWORK VIEWED FROM TOP SIDE" at -228.5,-655.67 h60
  text "BOARD #:" at 2248,-655.67 h60
  text ".PRJ_Number" at 2793.5,-655.67 h60
  text "REV:" at 3638,-655.67 h60
  text ".PCB_Rev" at 3929.5,-655.67 h60
  text "SVN REV:" at 4476,-655.67 h60
  text ".VersionControl_RevNumber" at 4982,-655.67 h60
  text "LAYER NAME =" at -228.5,-858.49 h60
  text "TID #:" at 2248,-859 h60
  text ".TID" at 2793.5,-859 h60
  text "PLOT NAME =" at -228.5,-1064.34 h60
  text ".plot_File_Name" at 577,-1064.34 h60
  text "GENERATED    :" at 2250,-1064.34 h60
  text ".Print_Date" at 3119.5,-1064.34 h60
  text ".Print_Time" at 3848.5,-1064.34 h60
  text "TEXAS INSTRUMENTS" at 5113,-1064.34 h60
M12 Stackup:
  drawing of 191 lines, arcs and shapes, not listed
  text "Layer" at 9790.58,7830 h60
  text "Name" at 10200.49,7830 h60
  text "Material" at 11130.23,7830 h60
  text "Thickness" at 11990,7830 h60
  text "Constant" at 12639.84,7830 h60
  text "Board Layer Stack" at 13209.7,7830 h60
  text "1" at 9790.58,7710 h60
  text "Top Overlay" at 10200.49,7710 h60
  text "2" at 9790.58,7590 h60
  text "Top Solder" at 10200.49,7590 h60
  text "Solder Resist" at 11130.23,7590 h60
  text "0.40mil" at 11990,7590 h60
  text "3.5" at 12639.84,7590 h60
  text "3" at 9790.58,7470 h60
  text "Top Layer" at 10200.49,7470 h60
  text "Copper" at 11130.23,7470 h60
  text "1.40mil" at 11990,7470 h60
  text "4" at 9790.58,7350 h60
  text "Dielectric1" at 10200.49,7350 h60
  text "FR-4" at 11130.23,7350 h60
  text "59.20mil" at 11990,7350 h60
  text "4.8" at 12639.84,7350 h60
  text "5" at 9790.58,7230 h60
  text "Bottom Layer" at 10200.49,7230 h60
  text "Copper" at 11130.23,7230 h60
  text "1.40mil" at 11990,7230 h60
  text "6" at 9790.58,7110 h60
  text "Bottom Solder" at 10200.49,7110 h60
  text "Solder Resist" at 11130.23,7110 h60
  text "0.40mil" at 11990,7110 h60
  text "3.5" at 12639.84,7110 h60
  text "7" at 9790.58,6990 h60
  text "Bottom Overlay" at 10200.49,6990 h60
  text ".Layer_Name" at 577,-858.49 h60
M13 Component Bodies Top:
  text ".Layer_Name" at 577,-858.49 h60
M14 Component Bodies Bottom:
  text ".Layer_Name" at 577,-858.49 h60
M15 Courtyards Top:
  text ".Layer_Name" at 577,-858.49 h60
M16 Courtyards Bottom:
  text ".Layer_Name" at 577,-858.49 h60
Drill Drawing:
  lines w1: 5537.05,2906.57 5578.54,2906.57 5557.8,2865.09 5537.05,2906.57 ; 5537.05,2989.53 5578.54,2989.53 5578.54,3031.02 5537.05,3031.02 5537.05,2989.53 ; 5537.05,3113.98 5557.8,3124.36 5578.54,3113.98 5568.17,3134.73 5578.54,3155.47 5557.8,3145.1 5537.05,3155.47 5547.42,3134.73 5537.05,3113.98 ; 5537.05,3248.81 5547.42,3248.81 5557.8,3238.44 5568.17,3248.81 5578.54,3248.81 5568.17,3259.18 5578.54,3269.55 5568.17,3269.55 5557.8,3279.92 5547.42,3269.55 5537.05,3269.55 5547.42,3259.18 5537.05,3248.81
  lines w10: 1300,0 0,0 0,2800 1300,2800 ; 1400,10 1400,2810
  lines w12: 5480,2827.75 7509.36,2827.75 ; 5480,3325.55 7509.36,3325.55 ; 5828.16,2703.3 5828.16,3450 ; 6170.27,2703.3 6170.27,3450 ; 6817.27,2703.3 6817.27,3450 ; 7086.62,2703.3 7086.62,3450 ; 5480,2703.3 7509.36,2703.3 7509.36,3450 5480,3450 5480,2703.3
  text "Symbol" at 5554.67,3362.89 h72
  text "Quantity" at 5865.5,3362.89 h72
  text "Finished Hole Size" at 6207.6,3362.89 h72
  text "Plated" at 6854.6,3362.89 h72
  text "Hole Type" at 7123.95,3362.89 h72
  text "1" at 5865.5,3238.44 h60
  text "77.95mil (1.980mm)" at 6207.6,3238.44 h60
  text "NPTH" at 6854.6,3238.44 h60
  text "Round" at 7123.95,3238.44 h60
  text "5" at 5865.5,3113.98 h60
  text "8.00mil (0.203mm)" at 6207.6,3113.98 h60
  text "PTH" at 6854.6,3113.98 h60
  text "Round" at 7123.95,3113.98 h60
  text "14" at 5865.5,2989.53 h60
  text "28.00mil (0.711mm)" at 6207.6,2989.53 h60
  text "PTH" at 6854.6,2989.53 h60
  text "Round" at 7123.95,2989.53 h60
  text "2" at 5865.5,2865.09 h60
  text "46.85mil (1.190mm)" at 6207.6,2865.09 h60
  text "PTH" at 6854.6,2865.09 h60
  text "Round" at 7123.95,2865.09 h60
  text "22 Total" at 5865.5,2740.64 h60
  text ".Layer_Name" at 577,-858.49 h60

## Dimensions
0,0 to 0,2800 on M2 Board Dimensions
0,0 to 1400,0 on M2 Board Dimensions
0,-400 to 1000,-400 on M2 Board Dimensions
